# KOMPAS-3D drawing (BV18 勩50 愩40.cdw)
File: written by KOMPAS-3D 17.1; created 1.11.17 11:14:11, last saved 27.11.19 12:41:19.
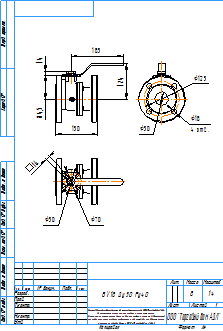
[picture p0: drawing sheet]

Sheet 1: A4, portrait

Title block, sheet 1: name: BV18 Ду50 Ру40; mass: 8; sheets: 1; sheet format: A4; stored path: C:\Users\kka\KOMPAS_Work\!Trash\BV18\KOMPAS 2D\BV18 Ду50 Ру40.cdw

Views: Проекционный вид 4, Проекционный вид 6
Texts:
  kka
  adl
  Рама для чертежей
  Лит-Масса-Масштаб
  Материал-Предприятие
  Масштаб
  Изм.
  Лист
  № докум.
  Подп.
  Дата
  Лит.
  Разраб.
  Пров.
  Т.контр.
  Листов
  Внимание! Данный продукт является объектом авторского права ООО «Торговый Дом АДЛ».
  Запрещается изменение, копирование, распространение
  (в том числе путем копирования на другие сайты и ресурсы в Интернете)
  или любое иное использование информации и объектов без предварительного
  согласия правообладателя (ООО «Торговый Дом АДЛ»).
  Н.контр.
  Утв.
  ООО "Торговый дом АДЛ"
  Изменение
  Номер документа
  Подпись
  Обозначение документа
  Наименование изделия
  Масса изделия по ГОСТ 2.109-73
  Порядковый номер листа
  Общее количество листов в документе
  Характер работы, выполненной лицом, подписавшим документ
  Наименование или индекс предприятия, выпускающего документ
  Инв. № подл.
  Подп. и дата
  Взам. инв. №
  Инв. № дубл.
  Инвентарный номер подлинника по ГОСТ 2.501-68
  Подпись принявшего подлинник в отдел технической документации
  Инвентарный номер подлинника, взамен которого выпущен данный подлинник
  Инвентарный номер дубликата по ГОСТ 2.502-68
  Подпись принявшего дубликат в отдел технической документации
  Справ. №
  Перв. примен.
  Обозначение документа, взамен или на основании которого выпущен данный документ
  Обозначение документа, в котором впервые записан данный документ
  Подпись лица, копировавшего чертеж
  Обозначение формата листа
  !Рама для чертежа
Dimensions and other numbers on the sheet: 150; 84,5; 14; 185; 124; 70; 50; 1:4; 1; 8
